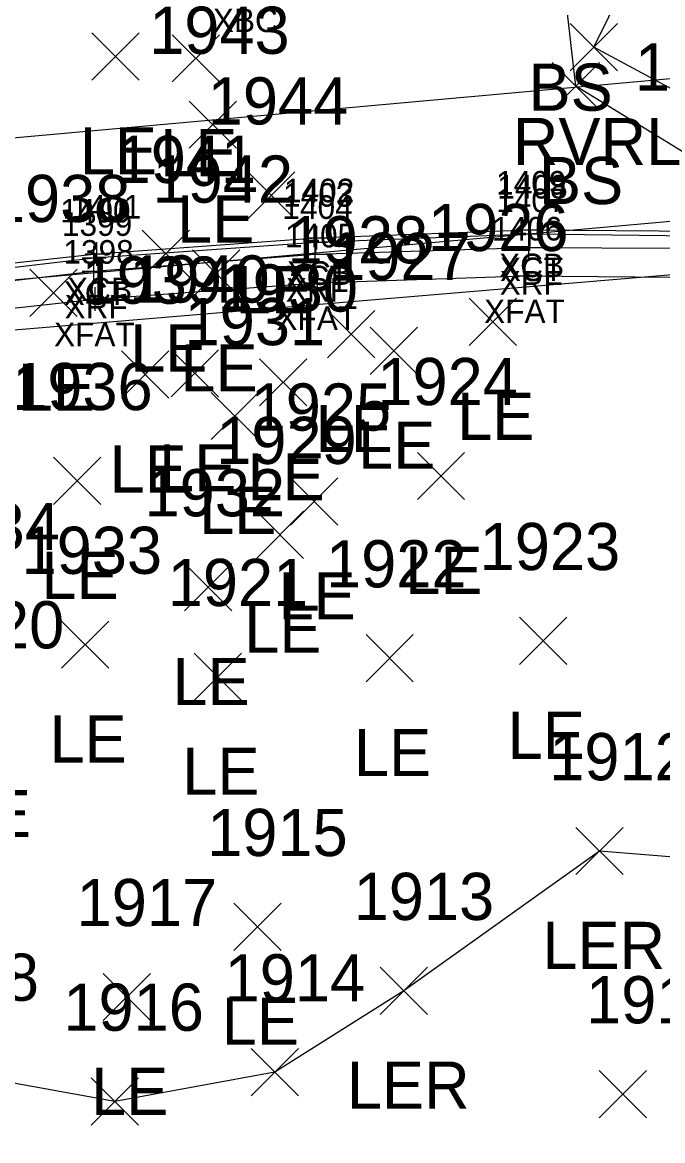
# Model space of a CAD drawing. Extents: x 1638344 to 1639591, y 610835 to 612202.
# Drawn here: x 1638686.84 to 1638713.96, y 611654.31 to 611701.7 of the extents above; entities that cross this region are included whole.
import ezdxf

# ---------------------------------------------------------------- set-up
doc = ezdxf.new("R2010")
doc.units = 0
for name, color, linetype in [('B_A', 7, 'Continuous'), ('B_I', 7, 'Continuous'), ('B_TIC', 7, 'Continuous'), ('BB', 7, 'Continuous'), ('BDC', 7, 'Continuous'), ('BF', 7, 'Continuous'), ('BR', 7, 'Continuous'), ('L_A', 7, 'Continuous'), ('L_I', 7, 'Continuous'), ('L_TIC', 7, 'Continuous'), ('LARO', 7, 'Continuous'), ('LAWE', 7, 'Continuous'), ('LELB', 7, 'Continuous'), ('USA', 7, 'Continuous')]:
    doc.layers.add(name, color=color, linetype=linetype)

msp = doc.modelspace()

# ---------------------------------------------------------------- linework, layer by layer
at = {"layer": 'B_TIC'}
for p, q in [((1638699.314, 611692.574), (1638699.39, 611692.574)), ((1638708.3, 611692.901), (1638708.376, 611692.901)), ((1638708.351, 611692.733), (1638708.426, 611692.733)), ((1638699.275, 611692.389), (1638699.351, 611692.389)), ((1638708.3, 611692.159), (1638708.376, 611692.159)), ((1638689.88, 611691.72), (1638689.956, 611691.72)), ((1638690.005, 611691.885), (1638690.08, 611691.885)), ((1638699.246, 611691.87), (1638699.322, 611691.87)), ((1638689.876, 611691.151), (1638689.952, 611691.151)), ((1638708.146, 611690.955), (1638708.222, 611690.955)), ((1638699.351, 611690.662), (1638699.427, 611690.662)), ((1638689.933, 611689.972), (1638690.009, 611689.972))]:
    msp.add_line(p, q, dxfattribs=at)
for points in [[(1638699.311, 611692.074), (1638699.311, 611693.074)], [(1638708.297, 611692.401), (1638708.297, 611693.401)], [(1638708.347, 611692.233), (1638708.347, 611693.233)], [(1638698.811, 611692.574), (1638699.811, 611692.574)], [(1638699.272, 611691.889), (1638699.272, 611692.889)], [(1638707.797, 611692.901), (1638708.797, 611692.901)], [(1638707.847, 611692.733), (1638708.847, 611692.733)], [(1638708.297, 611691.659), (1638708.297, 611692.659)], [(1638689.877, 611691.22), (1638689.877, 611692.22)], [(1638690.001, 611691.385), (1638690.001, 611692.385)], [(1638698.772, 611692.389), (1638699.772, 611692.389)], [(1638699.243, 611691.37), (1638699.243, 611692.37)], [(1638707.797, 611692.159), (1638708.797, 611692.159)], [(1638689.377, 611691.72), (1638690.377, 611691.72)], [(1638689.501, 611691.885), (1638690.501, 611691.885)], [(1638689.873, 611690.651), (1638689.873, 611691.651)], [(1638698.743, 611691.87), (1638699.743, 611691.87)], [(1638689.373, 611691.151), (1638690.373, 611691.151)], [(1638699.348, 611690.162), (1638699.348, 611691.162)], [(1638708.143, 611690.455), (1638708.143, 611691.455)], [(1638707.643, 611690.955), (1638708.643, 611690.955)], [(1638689.93, 611689.472), (1638689.93, 611690.472)], [(1638698.848, 611690.662), (1638699.848, 611690.662)], [(1638689.43, 611689.972), (1638690.43, 611689.972)]]:
    msp.add_lwpolyline(points, dxfattribs=at)
at = {"layer": 'BB'}
for points in [[(1638735.113, 611701.19), (1638645.728, 611693.119)], [(1638735.024, 611695.116), (1638645.767, 611687.143)]]:
    msp.add_lwpolyline(points, dxfattribs=at)
at = {"layer": 'BDC'}
for points in [[(1638643.605, 611680.783), (1638643.689, 611681.951), (1638643.879, 611682.479), (1638644.906, 611683.054), (1638653.74, 611685.572), (1638662.565, 611687.676), (1638671.519, 611689.446), (1638680.775, 611690.884), (1638690.001, 611691.885), (1638699.311, 611692.574), (1638708.297, 611692.901), (1638717.491, 611692.832), (1638726.752, 611692.352), (1638735.95, 611691.657), (1638737.129, 611691.067), (1638737.223, 611690.511), (1638737.312, 611689.575)], [(1638643.799, 611680.907), (1638643.873, 611682.03), (1638644.045, 611682.341), (1638644.871, 611682.816), (1638653.777, 611685.254), (1638662.653, 611687.522), (1638671.563, 611689.245), (1638680.795, 611690.65), (1638689.877, 611691.72), (1638699.272, 611692.389), (1638708.347, 611692.733), (1638717.562, 611692.619), (1638726.79, 611692.204), (1638735.927, 611691.309), (1638736.985, 611690.971), (1638737.095, 611690.437), (1638737.028, 611689.623)]]:
    msp.add_lwpolyline(points, dxfattribs=at)
at = {"layer": 'BF'}
msp.add_lwpolyline([(1638643.799, 611680.907), (1638653.718, 611683.594), (1638662.777, 611685.814), (1638671.812, 611687.579), (1638680.875, 611688.98), (1638689.93, 611689.972), (1638699.348, 611690.662), (1638708.143, 611690.955), (1638717.439, 611690.875), (1638726.565, 611690.452), (1638737.028, 611689.623)], dxfattribs=at)
at = {"layer": 'BR'}
msp.add_lwpolyline([(1638644.399, 611681.219), (1638644.188, 611682.086), (1638653.403, 611684.664), (1638662.762, 611686.927), (1638671.475, 611688.673), (1638680.941, 611690.128), (1638689.873, 611691.151), (1638699.243, 611691.87), (1638708.297, 611692.159), (1638717.569, 611692.113), (1638726.726, 611691.593), (1638736.49, 611690.72), (1638736.503, 611689.87)], dxfattribs=at)
at = {"layer": 'L_TIC'}
for points in [[(1638710.048, 611699.649), (1638712.048, 611701.649)], [(1638712.048, 611699.649), (1638710.048, 611701.649)], [(1638689.789, 611699.257), (1638691.789, 611701.257)], [(1638691.789, 611699.257), (1638689.789, 611701.257)], [(1638693.194, 611699.176), (1638695.194, 611701.176)], [(1638695.194, 611699.176), (1638693.194, 611701.176)], [(1638709.279, 611697.997), (1638711.279, 611699.997)], [(1638711.279, 611697.997), (1638709.279, 611699.997)], [(1638693.906, 611696.365), (1638695.906, 611698.365)], [(1638695.906, 611696.365), (1638693.906, 611698.365)], [(1638696.387, 611693.371), (1638698.387, 611695.371)], [(1638698.387, 611693.371), (1638696.387, 611695.371)], [(1638691.92, 611690.896), (1638693.92, 611692.896)], [(1638693.92, 611690.896), (1638691.92, 611692.896)], [(1638694.051, 611690.058), (1638696.051, 611692.058)], [(1638696.051, 611690.058), (1638694.051, 611692.058)], [(1638687.161, 611689.238), (1638689.161, 611691.238)], [(1638689.161, 611689.238), (1638687.161, 611691.238)], [(1638705.77, 611688.008), (1638707.77, 611690.008)], [(1638707.77, 611688.008), (1638705.77, 611690.008)], [(1638699.772, 611687.487), (1638701.772, 611689.487)], [(1638701.772, 611687.487), (1638699.772, 611689.487)], [(1638701.573, 611686.781), (1638703.573, 611688.781)], [(1638703.573, 611686.781), (1638701.573, 611688.781)], [(1638693.146, 611685.824), (1638695.146, 611687.824)], [(1638695.146, 611685.824), (1638693.146, 611687.824)], [(1638691.048, 611685.776), (1638693.048, 611687.776)], [(1638693.048, 611685.776), (1638691.048, 611687.776)], [(1638696.886, 611685.443), (1638698.886, 611687.443)], [(1638698.886, 611685.443), (1638696.886, 611687.443)], [(1638694.841, 611684.018), (1638696.841, 611686.018)], [(1638696.841, 611684.018), (1638694.841, 611686.018)], [(1638688.161, 611681.267), (1638690.161, 611683.267)], [(1638690.161, 611681.267), (1638688.161, 611683.267)], [(1638703.571, 611681.478), (1638705.571, 611683.478)], [(1638705.571, 611681.478), (1638703.571, 611683.478)], [(1638698.203, 611680.398), (1638700.203, 611682.398)], [(1638700.203, 611680.398), (1638698.203, 611682.398)], [(1638696.754, 611678.986), (1638698.754, 611680.986)], [(1638698.754, 611678.986), (1638696.754, 611680.986)], [(1638693.712, 611676.766), (1638695.712, 611678.766)], [(1638695.712, 611676.766), (1638693.712, 611678.766)], [(1638707.904, 611674.487), (1638709.904, 611676.487)], [(1638709.904, 611674.487), (1638707.904, 611676.487)], [(1638688.504, 611674.327), (1638690.504, 611676.327)], [(1638690.504, 611674.327), (1638688.504, 611676.327)], [(1638701.397, 611673.755), (1638703.397, 611675.755)], [(1638703.397, 611673.755), (1638701.397, 611675.755)], [(1638694.126, 611672.964), (1638696.126, 611674.964)], [(1638696.126, 611672.964), (1638694.126, 611674.964)], [(1638710.282, 611665.582), (1638712.282, 611667.582)], [(1638712.282, 611665.582), (1638710.282, 611667.582)], [(1638695.797, 611662.37), (1638697.797, 611664.37)], [(1638697.797, 611662.37), (1638695.797, 611664.37)], [(1638690.268, 611659.399), (1638692.268, 611661.399)], [(1638692.268, 611659.399), (1638690.268, 611661.399)], [(1638702.001, 611659.659), (1638704.001, 611661.659)], [(1638704.001, 611659.659), (1638702.001, 611661.659)], [(1638696.535, 611656.21), (1638698.535, 611658.21)], [(1638698.535, 611656.21), (1638696.535, 611658.21)], [(1638711.276, 611655.28), (1638713.276, 611657.28)], [(1638713.276, 611655.28), (1638711.276, 611657.28)], [(1638689.762, 611654.965), (1638691.762, 611656.965)], [(1638691.762, 611654.965), (1638689.762, 611656.965)]]:
    msp.add_lwpolyline(points, dxfattribs=at)
at = {"layer": 'LARO'}
msp.add_lwpolyline([(1638720.387, 611665.845), (1638711.282, 611666.582), (1638703.001, 611660.659), (1638697.535, 611657.21), (1638690.762, 611655.965), (1638683.724, 611657.237), (1638681.669, 611658.631)], dxfattribs=at)
at = {"layer": 'LAWE'}
msp.add_lwpolyline([(1638671.011, 611601.41), (1638687.934, 611612.159), (1638702.816, 611621.305), (1638722.828, 611637.898), (1638722.694, 611666.366), (1638723.119, 611679.868), (1638719.094, 611692.553), (1638717.187, 611697.341), (1638711.048, 611700.649), (1638718.685, 611716.114), (1638719.359, 611723.061), (1638714.323, 611734.571), (1638714.704, 611747.214), (1638712.56, 611755.84), (1638714.994, 611761.22), (1638711.865, 611767.72), (1638710.522, 611777.786), (1638714.936, 611789.326), (1638716.942, 611806.826), (1638715.698, 611824.36)], dxfattribs=at)
at = {"layer": 'LELB'}
msp.add_lwpolyline([(1638721.028, 611680.57), (1638715.476, 611695.81), (1638710.279, 611698.997), (1638709.836, 611702.955), (1638709.677, 611706.854), (1638712.785, 611716.361), (1638711.261, 611727.073), (1638708.812, 611734.706), (1638707.325, 611746.484), (1638710.104, 611757.938)], dxfattribs=at)
at = {"layer": 'USA'}
msp.add_lwpolyline([(1638734.852, 611692.726), (1638646.038, 611685.254)], dxfattribs=at)

# ---------------------------------------------------------------- texts
at = {"layer": 'B_A'}
for s, p in [('XBC', (1638694.912, 611701.285)), ('XCB', (1638707.033, 611690.901)), ('XCT', (1638707.068, 611690.733)), ('XCT', (1638697.992, 611690.389)), ('XCB', (1638698.047, 611690.574)), ('XRF', (1638707.057, 611690.159)), ('XCT', (1638688.597, 611689.72)), ('XCB', (1638688.737, 611689.885)), ('XRF', (1638698.003, 611689.87)), ('XRF', (1638688.632, 611689.151)), ('XFAT', (1638706.399, 611688.955)), ('XFAT', (1638697.604, 611688.662)), ('XFAT', (1638688.186, 611687.972))]:
    msp.add_text(s, height=1, dxfattribs=at).set_placement(p)
at = {"layer": 'B_I'}
for s, p in [('1409', (1638706.907, 611694.401)), ('1402', (1638697.925, 611694.074)), ('1408', (1638706.961, 611694.233)), ('1403', (1638697.886, 611693.889)), ('1407', (1638706.911, 611693.659)), ('1400', (1638688.448, 611693.22)), ('1401', (1638688.899, 611693.385)), ('1404', (1638697.857, 611693.37)), ('1399', (1638688.522, 611692.651)), ('1405', (1638697.962, 611692.162)), ('1406', (1638706.729, 611692.455)), ('1398', (1638688.583, 611691.472))]:
    msp.add_text(s, height=1, dxfattribs=at).set_placement(p)
at = {"layer": 'L_A'}
for s, p in [('BS', (1638708.277, 611697.955)), ('RVRL', (1638707.615, 611695.649)), ('LE', (1638689.277, 611695.257)), ('LE', (1638692.682, 611695.176)), ('BS', (1638708.72, 611693.997)), ('LE', (1638693.394, 611692.365)), ('LE', (1638695.875, 611689.371)), ('LE', (1638691.408, 611686.896)), ('LE', (1638693.539, 611686.058)), ('LE', (1638686.649, 611685.238)), ('LE', (1638705.258, 611684.008)), ('LE', (1638699.26, 611683.487)), ('LE', (1638701.061, 611682.781)), ('LE', (1638690.536, 611681.776)), ('LE', (1638692.634, 611681.824)), ('LE', (1638696.374, 611681.443)), ('LE', (1638694.33, 611680.018)), ('LE', (1638703.059, 611677.478)), ('LE', (1638687.649, 611677.267)), ('LE', (1638697.691, 611676.398)), ('LE', (1638696.242, 611674.986)), ('LE', (1638693.2, 611672.766)), ('LE', (1638687.992, 611670.327)), ('LE', (1638707.392, 611670.487)), ('LE', (1638700.885, 611669.755)), ('LE', (1638693.614, 611668.964)), ('LE', (1638683.935, 611667.17)), ('LER', (1638708.864, 611661.582)), ('LE', (1638695.285, 611658.37)), ('LER', (1638700.584, 611655.659)), ('LE', (1638689.756, 611655.399))]:
    msp.add_text(s, height=2, dxfattribs=at).set_placement(p)
at = {"layer": 'L_I'}
for s, p in [('1943', (1638692.213, 611700.365)), ('1877', (1638712.783, 611698.81)), ('1944', (1638694.694, 611697.371)), ('1941', (1638690.794, 611694.896)), ('1942', (1638692.358, 611694.058)), ('1938', (1638685.468, 611693.238)), ('1926', (1638704.022, 611692.008)), ('1928', (1638698.079, 611691.487)), ('1927', (1638699.88, 611690.781)), ('1939', (1638689.347, 611689.776)), ('1940', (1638691.366, 611689.824)), ('1930', (1638695.107, 611689.443)), ('1931', (1638693.715, 611688.018)), ('1924', (1638701.878, 611685.478)), ('1936', (1638686.413, 611685.267)), ('1925', (1638696.51, 611684.398)), ('1929', (1638695.053, 611682.986)), ('1932', (1638692.019, 611680.766)), ('1934', (1638682.482, 611679.338)), ('1933', (1638686.811, 611678.327)), ('1923', (1638706.211, 611678.487)), ('1922', (1638699.704, 611677.755)), ('1921', (1638693, 611676.964)), ('1920', (1638682.667, 611675.17)), ('1912', (1638709.156, 611669.582)), ('1915', (1638694.671, 611666.37)), ('1913', (1638700.875, 611663.659)), ('1917', (1638689.142, 611663.399)), ('1918', (1638681.598, 611660.237)), ('1914', (1638695.409, 611660.21)), ('1911', (1638710.717, 611659.28)), ('1916', (1638688.581, 611658.965))]:
    msp.add_text(s, height=2, dxfattribs=at).set_placement(p)

doc.saveas('drawing.dxf')
